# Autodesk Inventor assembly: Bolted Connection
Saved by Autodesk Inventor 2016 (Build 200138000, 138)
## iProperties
Created: 2016-01
Part Number: Bolted Connection
Document SubType Name: Assembly
Designer: Black Falcon
ClientObjectVersion: 1
Author: Black Falcon
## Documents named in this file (2)
- E:\Learning Inventor\Belt Friction Apparatus\Final Assembly\Design Accelerator\Bolted Connection2.iam
- C:\Users\Black Falcon\Documents\Inventor\Content Center Files\R2016\en-US\ANSI ASME B18.2.1(2)\ANSI_ASME B18.2.1 - 5_16-18 UNC - 1.25(2).ipt
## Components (1 placed, 1 different names)
1. Hex Bolt - Inch 5/16-18 UNC - 1.25:1
